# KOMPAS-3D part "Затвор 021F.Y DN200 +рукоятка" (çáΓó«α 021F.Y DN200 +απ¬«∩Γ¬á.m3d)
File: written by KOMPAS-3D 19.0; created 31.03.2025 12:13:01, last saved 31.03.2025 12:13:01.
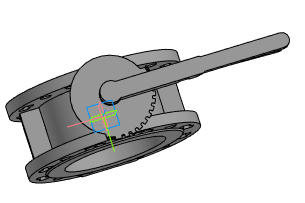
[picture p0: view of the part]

Document properties: Автор: Евгений; Полное имя файла: Затвор 021F.Y DN100 +рукоятка.a3d

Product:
- Part/product: Затвор 021F.Y DN200 +рукоятка
    Масса: 36.5879

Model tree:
1. Операция без истории:1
